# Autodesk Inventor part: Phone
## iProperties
Shininess: 64.0
Length Units: 11269
Angle Units: 11279
Time Units: 11290
Mass Units: 11283
Length Display Precision: 3
Angle Display Precision: 2
Compacted: True
Part Number: Phone
Document SubType Name: Modeling
Created: 2002-12
Designer: deepak
Density: 0.0
Volumn: 0.0
Area: 0.0
PropertySet Name: Model Information
Control State: 0
Master: False
Checked Out: False
Author: deepak
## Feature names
1. Loft1
2. Split1
3. Shell2
